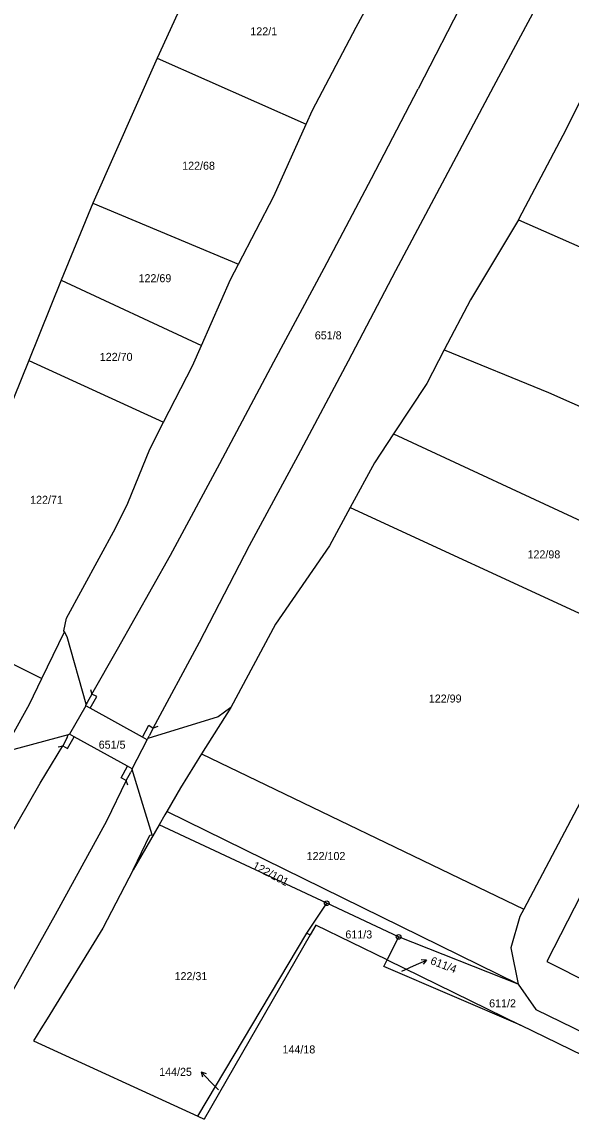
# Model space of a CAD drawing. Extents: x -783948 to -781889, y -1005870 to -1004430.
# Drawn here: x -783238.5 to -783122, y -1005216.9 to -1004983.9 of the extents above; entities that cross this region are included whole.
import ezdxf

# ---------------------------------------------------------------- set-up
doc = ezdxf.new("R2010")
doc.units = 0
for name, color, linetype in [('Vrstva 1', 7, 'Continuous'), ('Vrstva 2', 7, 'Continuous'), ('Vrstva 4', 7, 'Continuous'), ('Vrstva 7', 7, 'Continuous'), ('Vrstva 8', 7, 'Continuous')]:
    doc.layers.add(name, color=color, linetype=linetype)

msp = doc.modelspace()

# ---------------------------------------------------------------- linework, layer by layer
at = {"layer": 'Vrstva 1'}
for p, q in [((-783197.55, -1004964.59), (-783209.83, -1004991.59)), ((-783167.56, -1004984.95), (-783164.87, -1004979.99)), ((-783176.84, -1005002.64), (-783167.56, -1004984.95)), ((-783209.83, -1004991.59), (-783223.47, -1005022.33)), ((-783209.83, -1004991.59), (-783178.17, -1005005.6)), ((-783120.14, -1005000.99), (-783123.71, -1005007.98)), ((-783178.17, -1005005.6), (-783176.84, -1005002.64)), ((-783123.71, -1005007.98), (-783133.03, -1005025.7)), ((-783223.47, -1005022.33), (-783230.19, -1005038.73)), ((-783223.47, -1005022.33), (-783192.59, -1005035.32)), ((-783133.03, -1005025.7), (-783133.13, -1005025.87)), ((-783230.19, -1005038.73), (-783237.05, -1005055.76)), ((-783230.19, -1005038.73), (-783200.44, -1005052.62)), ((-783237.05, -1005055.76), (-783259.43, -1005110.88)), ((-783237.05, -1005055.76), (-783208.45, -1005068.86)), ((-783211.41, -1005074.64), (-783208.45, -1005068.86)), ((-783159.66, -1005071.37), (-783094.7, -1005101.6)), ((-783168.85, -1005087.02), (-783173.24, -1005095.15)), ((-783168.85, -1005087.02), (-783106.73, -1005115.68)), ((-783259.43, -1005110.88), (-783234.31, -1005123.3)), ((-783234.31, -1005123.3), (-783229.51, -1005113.39)), ((-783194.22, -1005129.46), (-783200.39, -1005139.32)), ((-783113.99, -1005138.16), (-783132.02, -1005172.33)), ((-783200.39, -1005139.32), (-783132.02, -1005172.33)), ((-783133.16, -1005188.2), (-783207.78, -1005151.54)), ((-783209.4, -1005154.36), (-783214.9, -1005163.93)), ((-783173.83, -1005171.05), (-783209.4, -1005154.36)), ((-783178.04, -1005177.37), (-783173.83, -1005171.05)), ((-783158.56, -1005178.2), (-783173.83, -1005171.05)), ((-783201.2, -1005216.27), (-783178.04, -1005177.37)), ((-783177.32, -1005177.74), (-783199.88, -1005216.88)), ((-783178.04, -1005177.37), (-783177.32, -1005177.74)), ((-783158.56, -1005178.2), (-783161.01, -1005183.09)), ((-783133.16, -1005188.2), (-783158.56, -1005178.2)), ((-783161.71, -1005184.48), (-783161.01, -1005183.09)), ((-783132.67, -1005196.94), (-783161.71, -1005184.48)), ((-783161.01, -1005183.09), (-783132.67, -1005196.94)), ((-783234.53, -1005197.72), (-783236.11, -1005200.27)), ((-783104.98, -1005210.52), (-783132.67, -1005196.94)), ((-783236.11, -1005200.27), (-783201.2, -1005216.27)), ((-783201.2, -1005216.27), (-783199.88, -1005216.88))]:
    msp.add_line(p, q, dxfattribs=at)
for points in [[(-783192.59, -1005035.32), (-783185.06, -1005020.89), (-783178.17, -1005005.6)], [(-783133.13, -1005025.87), (-783143.33, -1005042.92), (-783148.87, -1005053.52)], [(-783133.13, -1005025.87), (-783072.79, -1005052.47), (-783069.36, -1005053.58)], [(-783200.44, -1005052.62), (-783194.29, -1005038.57), (-783192.59, -1005035.32)], [(-783208.45, -1005068.86), (-783202.31, -1005056.9), (-783200.44, -1005052.62)], [(-783148.87, -1005053.52), (-783152.61, -1005060.68), (-783159.66, -1005071.37)], [(-783148.87, -1005053.52), (-783126.73, -1005062.56), (-783084.07, -1005081.46)], [(-783159.66, -1005071.37), (-783163.7, -1005077.5), (-783168.85, -1005087.02)], [(-783229.51, -1005113.39), (-783229.61, -1005113.2), (-783229.11, -1005110.52), (-783218.71, -1005091.37), (-783216.08, -1005086.1), (-783211.41, -1005074.64)], [(-783173.24, -1005095.15), (-783184.69, -1005111.78), (-783194.22, -1005129.46)], [(-783224.95, -1005129.13), (-783224.92, -1005128.74), (-783228.91, -1005114.47), (-783229.51, -1005113.39)], [(-783240.91, -1005135.88), (-783236.96, -1005128.78), (-783234.31, -1005123.3)], [(-783211.94, -1005136.32), (-783212.92, -1005135.78), (-783224.06, -1005129.62), (-783224.95, -1005129.13)], [(-783194.22, -1005129.46), (-783196.86, -1005131.48), (-783211.81, -1005136.07), (-783211.94, -1005136.32)], [(-783228.42, -1005135.15), (-783228.69, -1005135.29), (-783238.39, -1005137.89), (-783242.37, -1005138.96), (-783242.28, -1005139.41), (-783242.99, -1005139.6)], [(-783215.16, -1005142.48), (-783216.14, -1005141.94), (-783227.47, -1005135.67), (-783228.42, -1005135.15)], [(-783200.39, -1005139.32), (-783204.89, -1005146.51), (-783207.78, -1005151.54)], [(-783214.9, -1005163.93), (-783211.36, -1005156.62), (-783210.91, -1005156.5), (-783212.87, -1005150.07), (-783215.13, -1005142.62), (-783215.16, -1005142.48)], [(-783207.78, -1005151.54), (-783208.21, -1005152.29), (-783209.4, -1005154.36)], [(-783112.53, -1005154.93), (-783127.1, -1005183.43), (-783098.55, -1005197.8)], [(-783214.9, -1005163.93), (-783221.33, -1005176.37), (-783233.18, -1005195.57), (-783234.53, -1005197.72)], [(-783132.02, -1005172.33), (-783132.84, -1005173.89), (-783134.75, -1005180.52), (-783133.16, -1005188.2)], [(-783161.01, -1005183.09), (-783176.14, -1005175.7), (-783177.32, -1005177.74)], [(-783133.16, -1005188.2), (-783129.43, -1005193.64), (-783102.96, -1005206.52)]]:
    msp.add_lwpolyline(points, dxfattribs=at)
at = {"layer": 'Vrstva 4'}
for p, q in [((-783142.74, -1004975.32), (-783154.41, -1004998.1)), ((-783138.35, -1004997.54), (-783129.5, -1004981.01)), ((-783164.32, -1005017.13), (-783154.41, -1004998.1)), ((-783148.7, -1005016.96), (-783138.35, -1004997.54)), ((-783174.37, -1005036.19), (-783164.32, -1005017.13)), ((-783159.14, -1005036.67), (-783148.7, -1005016.96)), ((-783185.08, -1005056.09), (-783174.37, -1005036.19)), ((-783169.2, -1005055.86), (-783159.14, -1005036.67)), ((-783196.49, -1005077.64), (-783185.08, -1005056.09)), ((-783179.9, -1005075.98), (-783169.2, -1005055.86)), ((-783206.97, -1005097.11), (-783196.49, -1005077.64)), ((-783190.2, -1005095.1), (-783179.9, -1005075.98)), ((-783200.84, -1005115.57), (-783190.2, -1005095.1)), ((-783218.22, -1005117.07), (-783206.97, -1005097.11)), ((-783223.69, -1005126.65), (-783218.22, -1005117.07)), ((-783210.66, -1005133.84), (-783200.84, -1005115.57)), ((-783223.69, -1005126.65), (-783224.67, -1005128.38)), ((-783223.95, -1005125.68), (-783223.69, -1005126.65)), ((-783222.67, -1005127.15), (-783223.69, -1005126.65)), ((-783224.95, -1005129.13), (-783228.42, -1005135.15)), ((-783224.67, -1005128.38), (-783224.92, -1005128.74)), ((-783224.06, -1005129.62), (-783222.67, -1005127.15)), ((-783212.92, -1005135.78), (-783211.58, -1005133.23)), ((-783211.58, -1005133.23), (-783210.66, -1005133.84)), ((-783210.66, -1005133.84), (-783211.5, -1005135.5)), ((-783209.71, -1005133.53), (-783210.66, -1005133.84)), ((-783228.96, -1005135.84), (-783229.87, -1005137.59)), ((-783228.96, -1005135.84), (-783228.69, -1005135.29)), ((-783228.87, -1005138.16), (-783227.47, -1005135.67)), ((-783211.81, -1005136.07), (-783211.5, -1005135.5)), ((-783234.67, -1005145.54), (-783229.87, -1005137.59)), ((-783230.85, -1005137.8), (-783229.87, -1005137.59)), ((-783229.87, -1005137.59), (-783228.87, -1005138.16)), ((-783215.16, -1005142.48), (-783211.94, -1005136.32)), ((-783217.45, -1005144.44), (-783216.14, -1005141.94)), ((-783216.41, -1005145), (-783215.45, -1005143.2)), ((-783215.13, -1005142.62), (-783215.45, -1005143.2)), ((-783246.9, -1005166.76), (-783234.67, -1005145.54)), ((-783216.41, -1005145), (-783220.57, -1005153.6)), ((-783216.41, -1005145), (-783217.45, -1005144.44)), ((-783216.08, -1005145.95), (-783216.41, -1005145)), ((-783220.57, -1005153.6), (-783231.45, -1005173.48)), ((-783231.45, -1005173.48), (-783241.83, -1005192))]:
    msp.add_line(p, q, dxfattribs=at)
at = {"layer": 'Vrstva 7'}
for p, q in [((-783157.88, -1005185.44), (-783155.41, -1005184.33)), ((-783155.41, -1005184.33), (-783152.67, -1005183.11)), ((-783152.67, -1005183.11), (-783153.79, -1005183.06)), ((-783152.67, -1005183.11), (-783153.38, -1005183.97)), ((-783198.42, -1005209.01), (-783200.51, -1005206.85)), ((-783200.51, -1005206.85), (-783199.45, -1005207.22)), ((-783200.51, -1005206.85), (-783200.17, -1005207.92)), ((-783196.8, -1005210.69), (-783198.42, -1005209.01))]:
    msp.add_line(p, q, dxfattribs=at)
at = {"layer": 'Vrstva 8'}
for centre, radius in [((-783173.83, -1005171.05), 0.5), ((-783173.83, -1005171.05), 0.0303), ((-783158.56, -1005178.2), 0.5), ((-783158.56, -1005178.2), 0.0303)]:
    msp.add_circle(centre, radius, dxfattribs=at)

# ---------------------------------------------------------------- texts
at = {"layer": 'Vrstva 2'}
for s, p in [('122/1', (-783190.05, -1004986.72)), ('122/68', (-783204.52, -1005015.26)), ('122/69', (-783213.78, -1005039.15)), ('651/8', (-783176.36, -1005051.28)), ('122/70', (-783222.01, -1005055.85)), ('122/71', (-783236.8, -1005086.21)), ('122/98', (-783131.2, -1005097.8)), ('122/99', (-783152.16, -1005128.42)), ('651/5', (-783222.24, -1005138.22)), ('122/102', (-783178.09, -1005161.87)), ('611/3', (-783169.87, -1005178.52)), ('122/31', (-783206.13, -1005187.38)), ('611/2', (-783139.35, -1005193.15)), ('144/18', (-783183.22, -1005202.94)), ('144/25', (-783209.4, -1005207.7))]:
    msp.add_text(s, height=1.7, dxfattribs=at).set_placement(p)
for s, rotation, p in [('122/101', 332, (-783189.75, -1005163.59)), ('611/4', 339, (-783151.97, -1005183.9))]:
    msp.add_text(s, height=1.7, rotation=rotation, dxfattribs=at).set_placement(p)

doc.saveas('drawing.dxf')
